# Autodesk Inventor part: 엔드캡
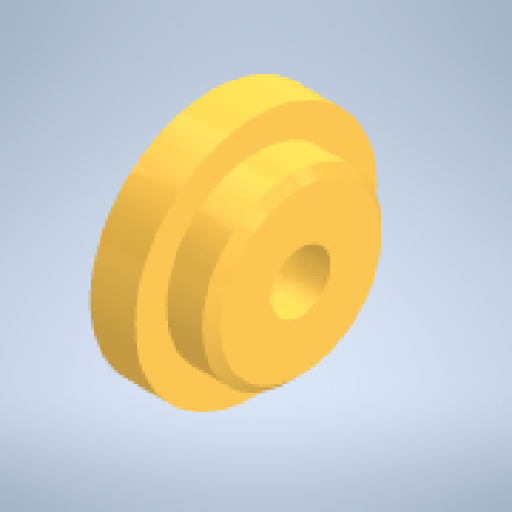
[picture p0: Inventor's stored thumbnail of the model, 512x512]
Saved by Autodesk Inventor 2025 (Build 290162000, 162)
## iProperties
Created: 2026-01
Part Number: 엔드캡
Material: 강철, 연강
Document SubType Name: Modeling
Designer: KDI
Density: 7.85 g/cm^3
Appearance: 기본값
Author: jhkim
Sending System: Autodesk Inventor 2026
Preprocessor: ST-DEVELOPER v20.1
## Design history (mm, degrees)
feature "솔리드1"
node "솔리드2"
